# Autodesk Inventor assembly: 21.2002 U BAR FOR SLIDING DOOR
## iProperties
Created: 2007-05
Part Number: 21.2002 U BAR FOR SLIDING DOOR
Document SubType Name: Assembly
Designer: Andy Moles
Author: Andy Moles
